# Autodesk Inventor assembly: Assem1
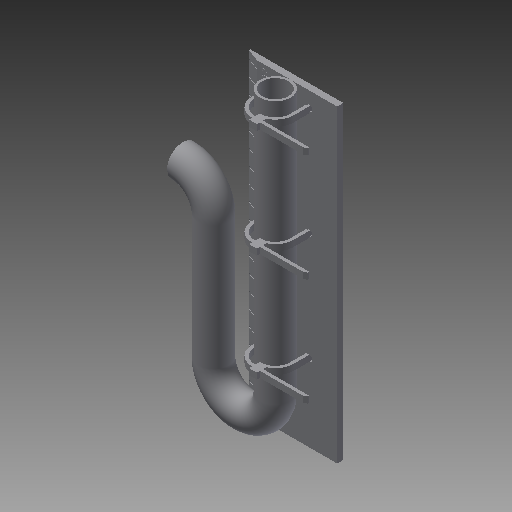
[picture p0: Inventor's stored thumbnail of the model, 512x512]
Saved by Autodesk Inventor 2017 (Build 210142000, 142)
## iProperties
Created: 2020-03
Part Number: Assem1
Description: STEP AP203
Document SubType Name: Assembly
Designer: user
Sending System: SolidWorks 2018
Preprocessor: SwSTEP 2.0
Title: Assem1.STEP
Revision Number: ANY
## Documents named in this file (4)
- C:\Users\user\Documents\Inventor\Home Ventilator CPAP\Assem1.iam
- C:\Users\user\Downloads\Ruler.ipt
- C:\Users\user\Downloads\Tube.ipt
- C:\Users\user\Downloads\ziptie.ipt
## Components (5 placed, 5 different names)
1. Ruler_1
2. Tube_2
3. ziptie_3
4. ziptie_4
5. ziptie_5
